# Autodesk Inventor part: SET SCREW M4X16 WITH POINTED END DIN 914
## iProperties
IsCustomPart: 1
Created: 2006-02
Part Number: SET SCREW M4X16 WITH POINTED END DIN 914
Material: Steel, Mild
Description: Hexagon Socket Set Screw
Document SubType Name: Modeling
Standard: DIN 914
Designer: Andy Moles
Standards Organization: DIN
Language: en-US
Size Designation: M4 x 16
Categories: <MemberInstance><Categories><Category DisplayName="Fasteners" InternalName="e4da775c-781d-43d5-af7c-5136215cf5a6" Mnemonic="FSTN"><Category DisplayName="Bolts"
Density: 7.86 g/cm^3
Author: Andy Moles
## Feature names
1. Body [Revolution]
2. Slot [Extrusion]
3. Chamfer1
4. Chamfer2
